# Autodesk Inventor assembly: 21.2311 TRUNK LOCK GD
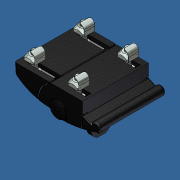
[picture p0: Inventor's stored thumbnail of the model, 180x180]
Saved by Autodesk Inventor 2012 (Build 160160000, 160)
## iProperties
Created: 2014-09
Part Number: 21.2311 TRUNK LOCK GD
Document SubType Name: Assembly
Designer: Admin
Art.-Nr.: 21.2311/0
L: -
Stück: 1
5: Fallenverschluss compact
7: 21.2311/0
8: MiniTec Maschinenbau GmbH & Co KG
Author: Admin
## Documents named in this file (11)
- C:\Andys Backup Data\ANDY'S INVENTOR\INVENTOR LIBRARIES\PARTS LIBRARY\HANDLES LOCKS STOPS\21.2311 TRUNK LOCK GD.iam
- C:\Andys Backup Data\ANDY'S INVENTOR\INVENTOR LIBRARIES\PARTS LIBRARY\FASTENING ELEMENTS\NUTS\21.1330_2 M6 SQUARE NUT POS FXG.ipt
- C:\Andys Backup Data\ANDY'S INVENTOR\INVENTOR LIBRARIES\PARTS LIBRARY\FASTENING ELEMENTS\SCREWS CAP\21.1240 M6X20.ipt
- C:\Andys Backup Data\ANDY'S INVENTOR\INVENTOR LIBRARIES\PARTS LIBRARY\FASTENING ELEMENTS\WASHERS\21.1126 M6 ROUND WASHER.ipt
- C:\Andys Backup Data\ANDY'S INVENTOR\INVENTOR LIBRARIES\PARTS LIBRARY\HANDLES LOCKS STOPS\SUBCOMPONENTS\21.2311 TRUNK LOCK GD LEVER HANDLE.ipt
- C:\Andys Backup Data\ANDY'S INVENTOR\INVENTOR LIBRARIES\PARTS LIBRARY\HANDLES LOCKS STOPS\SUBCOMPONENTS\21.2311 TRUNK LOCK GD LOCK.ipt
- C:\Andys Backup Data\ANDY'S INVENTOR\INVENTOR LIBRARIES\PARTS LIBRARY\HANDLES LOCKS STOPS\SUBCOMPONENTS\21.2311 TRUNK LOCK GD LEVER SIDE MTG PLT.ipt
- C:\Andys Backup Data\ANDY'S INVENTOR\INVENTOR LIBRARIES\PARTS LIBRARY\HANDLES LOCKS STOPS\SUBCOMPONENTS\21.2311 TRUNK LOCK GD HANDLE SIDE CAP.ipt
- C:\Andys Backup Data\ANDY'S INVENTOR\INVENTOR LIBRARIES\PARTS LIBRARY\HANDLES LOCKS STOPS\SUBCOMPONENTS\21.2311 TRUNK LOCK GD CATCH.ipt
- C:\Andys Backup Data\ANDY'S INVENTOR\INVENTOR LIBRARIES\PARTS LIBRARY\HANDLES LOCKS STOPS\SUBCOMPONENTS\21.2311 TRUNK LOCK GD CATCH CAP.ipt
- C:\Andys Backup Data\ANDY'S INVENTOR\INVENTOR LIBRARIES\PARTS LIBRARY\HANDLES LOCKS STOPS\SUBCOMPONENTS\EMKA SUBCOMPONENTS\1108-U35_ASM.iam
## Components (21 placed, 10 different names)
1. 21.2311 TRUNK LOCK GD LEVER HANDLE:1 — Insert:5, Mate:20, Flush:3, Mate:21, Mate:22, Mate:26, Flush:6, Angle:10
2. 21.2311 TRUNK LOCK GD LEVER SIDE MTG PLT:1 — Mate:9, Mate:10, Mate:11, Angle:1, Angle:2, Angle:3, Angle:4, Angle:5, Angle:7, Angle:8, Mate:23, Flush:4, Flush:5, Mate:26, Flush:6, Angle:10
3. 21.2311 TRUNK LOCK GD CATCH:1 — Mate:12, Mate:13, Mate:14, Mate:16, Mate:17, Mate:18, Mate:19, Angle:6, Mate:23, Flush:4, Flush:5, Mate:24, Mate:25, Angle:9
4. 21.2311 TRUNK LOCK GD LOCK:1 — Mate:20, Flush:3, Angle:7, Mate:27, Angle:11, Mate:28, Mate:29
5. 21.2311 TRUNK LOCK GD HANDLE SIDE CAP:1 — Mate:21, Mate:22, Angle:8
6. 21.2311 TRUNK LOCK GD CATCH CAP:1 — Mate:24, Mate:25, Angle:9
7. 21.1330_2 M6 SQUARE NUT POS FXG:1 — Mate:1, Mate:2, Angle:3, Flush:2
8. 21.1330_2 M6 SQUARE NUT POS FXG:2 — Mate:3, Mate:4, Angle:4, Flush:2
9. 21.1330_2 M6 SQUARE NUT POS FXG:3 — Mate:5, Mate:6, Flush:1, Angle:1
10. 21.1330_2 M6 SQUARE NUT POS FXG:4 — Mate:7, Mate:8, Mate:9, Flush:1, Angle:2
11. 21.1240  M6x20 SHCS:1 — Insert:1, Mate:1, Mate:14, Mate:15
12. 21.1240  M6x20 SHCS:2 — Insert:2, Mate:3, Mate:17
13. 21.1240  M6x20 SHCS:3 — Insert:3, Mate:5, Mate:11, Mate:15
14. 21.1240  M6x20 SHCS:4 — Insert:4, Mate:7, Mate:10
15. 21.1126 M6 ROUND WASHER:1 — Insert:1, Mate:2, Mate:13
16. 21.1126 M6 ROUND WASHER:2 — Insert:2, Mate:4, Mate:12, Mate:16
17. 21.1126 M6 ROUND WASHER:3 — Insert:3, Mate:6
18. 21.1126 M6 ROUND WASHER:4 — Insert:4, Mate:8
19. 21.2311 TRUNK LOCK GD HANDLE SIDE CAP:2 — Insert:5, Angle:5
20. 21.2311 TRUNK LOCK GD CATCH CAP:2 — Mate:18, Mate:19, Angle:6
21. 1108-U35_ASM:1 [sub-assembly] — Mate:27, Angle:11, Mate:28, Mate:29
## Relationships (51: Mate 29, Angle 11, Flush 6, Insert 5)
- Insert:1: 21.1240  M6x20 SHCS:1 ↔ 21.1126 M6 ROUND WASHER:1
- Insert:2: 21.1240  M6x20 SHCS:2 ↔ 21.1126 M6 ROUND WASHER:2
- Insert:3: 21.1240  M6x20 SHCS:3 ↔ 21.1126 M6 ROUND WASHER:3
- Insert:4: 21.1240  M6x20 SHCS:4 ↔ 21.1126 M6 ROUND WASHER:4
- Mate:1: 21.1330_2 M6 SQUARE NUT POS FXG:1 ↔ 21.1240  M6x20 SHCS:1
- Mate:2: 21.1330_2 M6 SQUARE NUT POS FXG:1 ↔ 21.1126 M6 ROUND WASHER:1
- Mate:3: 21.1330_2 M6 SQUARE NUT POS FXG:2 ↔ 21.1240  M6x20 SHCS:2
- Mate:4: 21.1330_2 M6 SQUARE NUT POS FXG:2 ↔ 21.1126 M6 ROUND WASHER:2
- Mate:5: 21.1330_2 M6 SQUARE NUT POS FXG:3 ↔ 21.1240  M6x20 SHCS:3
- Mate:6: 21.1330_2 M6 SQUARE NUT POS FXG:3 ↔ 21.1126 M6 ROUND WASHER:3
- Mate:7: 21.1330_2 M6 SQUARE NUT POS FXG:4 ↔ 21.1240  M6x20 SHCS:4
- Mate:8: 21.1330_2 M6 SQUARE NUT POS FXG:4 ↔ 21.1126 M6 ROUND WASHER:4
- Mate:9: 21.2311 TRUNK LOCK GD LEVER SIDE MTG PLT:1 ↔ 21.1330_2 M6 SQUARE NUT POS FXG:4
- Mate:10: 21.2311 TRUNK LOCK GD LEVER SIDE MTG PLT:1 ↔ 21.1240  M6x20 SHCS:4
- Flush:1: 21.1330_2 M6 SQUARE NUT POS FXG:3 ↔ 21.1330_2 M6 SQUARE NUT POS FXG:4
- Mate:11: 21.2311 TRUNK LOCK GD LEVER SIDE MTG PLT:1 ↔ 21.1240  M6x20 SHCS:3
- Angle:1: 21.2311 TRUNK LOCK GD LEVER SIDE MTG PLT:1 ↔ 21.1330_2 M6 SQUARE NUT POS FXG:3
- Angle:2: 21.2311 TRUNK LOCK GD LEVER SIDE MTG PLT:1 ↔ 21.1330_2 M6 SQUARE NUT POS FXG:4
- Mate:12: 21.2311 TRUNK LOCK GD CATCH:1 ↔ 21.1126 M6 ROUND WASHER:2
- Mate:13: 21.2311 TRUNK LOCK GD CATCH:1 ↔ 21.1126 M6 ROUND WASHER:1
- Angle:3: 21.2311 TRUNK LOCK GD LEVER SIDE MTG PLT:1 ↔ 21.1330_2 M6 SQUARE NUT POS FXG:1
- Angle:4: 21.2311 TRUNK LOCK GD LEVER SIDE MTG PLT:1 ↔ 21.1330_2 M6 SQUARE NUT POS FXG:2
- Mate:14: 21.2311 TRUNK LOCK GD CATCH:1 ↔ 21.1240  M6x20 SHCS:1
- Mate:15: 21.1240  M6x20 SHCS:1 ↔ 21.1240  M6x20 SHCS:3
- Mate:16: 21.2311 TRUNK LOCK GD CATCH:1 ↔ 21.1126 M6 ROUND WASHER:2
- Mate:17: 21.2311 TRUNK LOCK GD CATCH:1 ↔ 21.1240  M6x20 SHCS:2
- Flush:2: 21.1330_2 M6 SQUARE NUT POS FXG:1 ↔ 21.1330_2 M6 SQUARE NUT POS FXG:2
- Insert:5: 21.2311 TRUNK LOCK GD LEVER HANDLE:1 ↔ 21.2311 TRUNK LOCK GD HANDLE SIDE CAP:2
- Angle:5: 21.2311 TRUNK LOCK GD LEVER SIDE MTG PLT:1 ↔ 21.2311 TRUNK LOCK GD HANDLE SIDE CAP:2
- Mate:18: 21.2311 TRUNK LOCK GD CATCH:1 ↔ 21.2311 TRUNK LOCK GD CATCH CAP:2
- Mate:19: 21.2311 TRUNK LOCK GD CATCH:1 ↔ 21.2311 TRUNK LOCK GD CATCH CAP:2
- Angle:6: 21.2311 TRUNK LOCK GD CATCH:1 ↔ 21.2311 TRUNK LOCK GD CATCH CAP:2
- Mate:20: 21.2311 TRUNK LOCK GD LEVER HANDLE:1 ↔ 21.2311 TRUNK LOCK GD LOCK:1
- Flush:3: 21.2311 TRUNK LOCK GD LEVER HANDLE:1 ↔ 21.2311 TRUNK LOCK GD LOCK:1
- Angle:7: 21.2311 TRUNK LOCK GD LEVER SIDE MTG PLT:1 ↔ 21.2311 TRUNK LOCK GD LOCK:1
- Mate:21: 21.2311 TRUNK LOCK GD LEVER HANDLE:1 ↔ 21.2311 TRUNK LOCK GD HANDLE SIDE CAP:1
- Mate:22: 21.2311 TRUNK LOCK GD LEVER HANDLE:1 ↔ 21.2311 TRUNK LOCK GD HANDLE SIDE CAP:1
- Angle:8: 21.2311 TRUNK LOCK GD LEVER SIDE MTG PLT:1 ↔ 21.2311 TRUNK LOCK GD HANDLE SIDE CAP:1
- Mate:23: 21.2311 TRUNK LOCK GD LEVER SIDE MTG PLT:1 ↔ 21.2311 TRUNK LOCK GD CATCH:1
- Flush:4: 21.2311 TRUNK LOCK GD LEVER SIDE MTG PLT:1 ↔ 21.2311 TRUNK LOCK GD CATCH:1
- Flush:5: 21.2311 TRUNK LOCK GD LEVER SIDE MTG PLT:1 ↔ 21.2311 TRUNK LOCK GD CATCH:1
- Mate:24: 21.2311 TRUNK LOCK GD CATCH:1 ↔ 21.2311 TRUNK LOCK GD CATCH CAP:1
- Mate:25: 21.2311 TRUNK LOCK GD CATCH:1 ↔ 21.2311 TRUNK LOCK GD CATCH CAP:1
- Angle:9: 21.2311 TRUNK LOCK GD CATCH:1 ↔ 21.2311 TRUNK LOCK GD CATCH CAP:1
- Mate:26: 21.2311 TRUNK LOCK GD LEVER HANDLE:1 ↔ 21.2311 TRUNK LOCK GD LEVER SIDE MTG PLT:1
- Flush:6: 21.2311 TRUNK LOCK GD LEVER HANDLE:1 ↔ 21.2311 TRUNK LOCK GD LEVER SIDE MTG PLT:1
- Angle:10: 21.2311 TRUNK LOCK GD LEVER HANDLE:1 ↔ 21.2311 TRUNK LOCK GD LEVER SIDE MTG PLT:1
- Mate:27: 21.2311 TRUNK LOCK GD LOCK:1 ↔ 1108-U35_ASM:1
- Angle:11: 21.2311 TRUNK LOCK GD LOCK:1 ↔ 1108-U35_ASM:1
- Mate:28: 21.2311 TRUNK LOCK GD LOCK:1 ↔ 1108-U35_ASM:1
- Mate:29: 21.2311 TRUNK LOCK GD LOCK:1 ↔ 1108-U35_ASM:1
